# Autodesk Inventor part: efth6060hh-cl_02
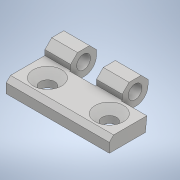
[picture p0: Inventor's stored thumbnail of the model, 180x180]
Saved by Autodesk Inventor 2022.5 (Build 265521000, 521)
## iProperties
Part Number: efth6060hh-cl_02
Material: 一般
Document SubType Name: Modeling
Designer: ImaoCorp
Density: 1 g/cm^3
Appearance: 既定
Author: ImaoCorp
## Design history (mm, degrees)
feature "efth6060hh-cl_02"
node "ソリッド1"
